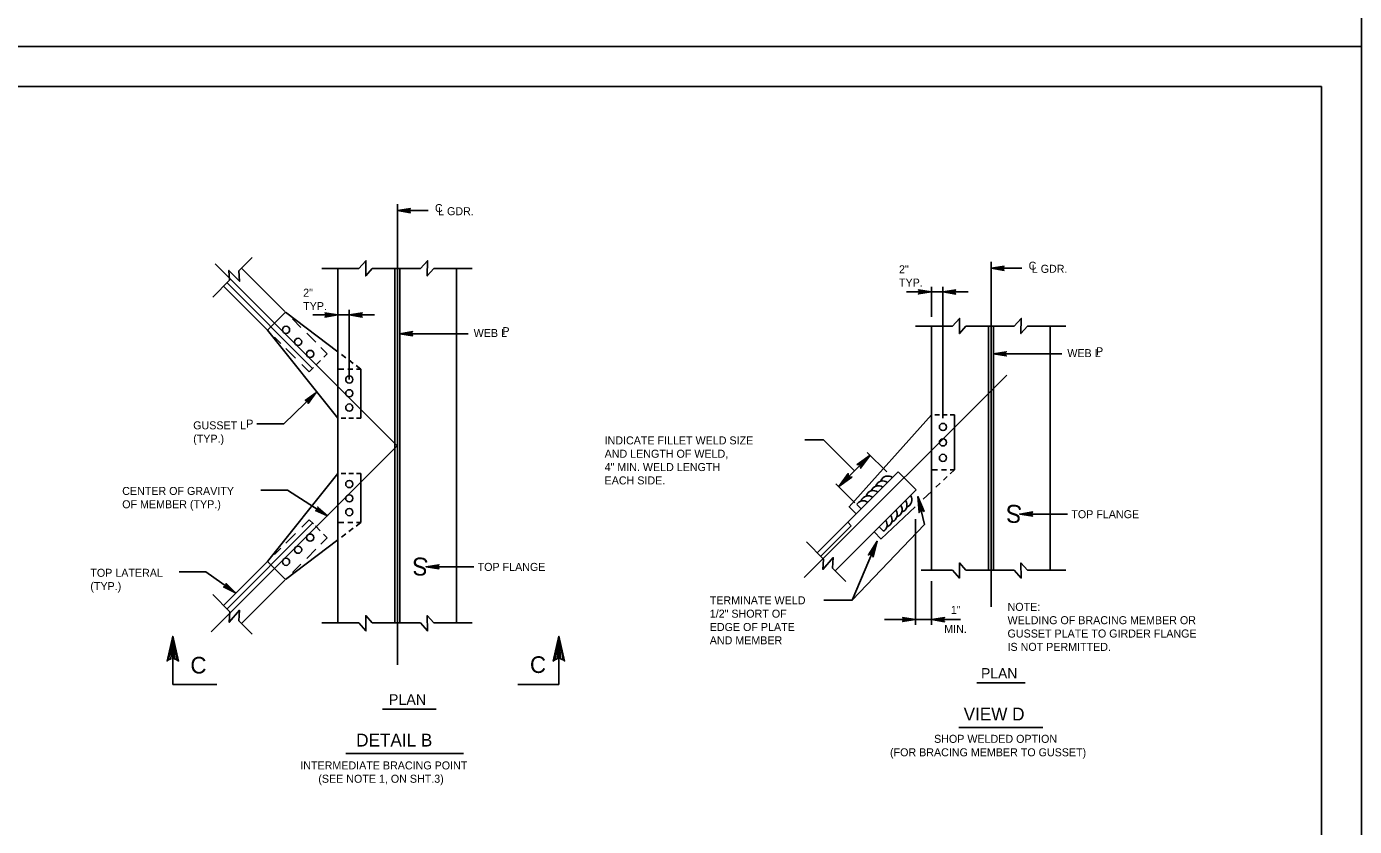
# Model space of a CAD drawing. Extents: x 30 to 2621, y -33 to 1155.
# Drawn here: x 1211.9 to 1709.8, y 268.6 to 568.5 of the extents above; entities that cross this region are included whole.
import ezdxf

# ---------------------------------------------------------------- set-up
doc = ezdxf.new("R2010")
doc.units = 0
doc.layers.add('1', color=7, linetype='Continuous')
doc.layers.add('PLT-BNDY', color=7, linetype='Continuous')

msp = doc.modelspace()

# ---------------------------------------------------------------- linework, layer by layer
at = {"layer": '1'}
for p, q in [((1697.5, 546), (911.5, 546)), ((1697.5, -18), (1697.5, 546)), ((1350.95, 492.79), (1350.95, 501.85)), ((1351.03, 499.48), (1362.48, 499.48)), ((1350.95, 329.19), (1350.95, 492.79)), ((1282.68, 479.55), (1350.92, 411.31)), ((1291.57, 476.94), (1296.56, 481.93)), ((1573.57, 471.19), (1573.57, 480.25)), ((1281.71, 467.08), (1288.05, 473.41)), ((1292.54, 477.91), (1308.82, 461.64)), ((1322.58, 477.74), (1336.53, 477.74)), ((1328.66, 344.89), (1328.66, 477.74)), ((1341.51, 477.74), (1359.63, 477.74)), ((1350, 477.74), (1350, 344.89)), ((1351.83, 477.74), (1351.83, 344.89)), ((1364.61, 477.74), (1378.98, 477.74)), ((1373.18, 344.89), (1373.18, 477.74)), ((1573.64, 477.87), (1585.09, 477.87)), ((1285.78, 471.15), (1302.22, 454.71)), ((1287.08, 472.45), (1319.19, 440.34)), ((1541.82, 469), (1555.46, 469)), ((1551.27, 459.7), (1551.27, 470.87)), ((1555.46, 421.65), (1555.46, 470.87)), ((1555.46, 469), (1564.96, 469)), ((1573.57, 350.96), (1573.57, 471.19)), ((1302.22, 454.71), (1308.98, 461.47)), ((1308.98, 461.47), (1328.66, 446.58)), ((1311.59, 458.86), (1314.8, 455.66)), ((1319.29, 460.36), (1332.93, 460.36)), ((1332.93, 436.17), (1332.93, 462.24)), ((1332.93, 460.36), (1342.44, 460.36)), ((1302.22, 454.71), (1328.66, 421.7)), ((1316.95, 453.5), (1320.35, 450.11)), ((1351.83, 453.33), (1377.46, 453.33)), ((1545.19, 456.14), (1559.14, 456.14)), ((1551.27, 364.65), (1551.27, 456.14)), ((1564.12, 456.14), (1582.24, 456.14)), ((1572.61, 456.14), (1572.61, 364.65)), ((1574.45, 456.14), (1574.45, 364.65)), ((1587.22, 456.14), (1601.59, 456.14)), ((1595.79, 364.65), (1595.79, 456.14)), ((1304.83, 452.1), (1307.27, 449.67)), ((1322.32, 448.14), (1324.65, 445.8)), ((1309.11, 447.83), (1312.8, 444.13)), ((1320.52, 441.67), (1322.18, 443.34)), ((1323.39, 444.54), (1324.65, 445.8)), ((1330.05, 445.53), (1331.61, 444.34)), ((1332.73, 443.5), (1334.41, 442.23)), ((1574.45, 445.79), (1600.07, 445.79)), ((1315.15, 441.79), (1317.89, 439.04)), ((1317.89, 439.04), (1319.45, 440.61)), ((1328.66, 440.11), (1330.94, 440.11)), ((1332.37, 440.11), (1334.28, 440.11)), ((1335.45, 441.44), (1337.2, 440.11)), ((1335.63, 440.11), (1337.2, 440.11)), ((1337.2, 440.11), (1337.2, 421.7)), ((1503.54, 361.89), (1579.43, 437.78)), ((1308.4, 419.61), (1320.44, 431.13)), ((1298.3, 419.61), (1308.4, 419.61)), ((1329.93, 421.7), (1331.58, 421.7)), ((1332.82, 421.7), (1334.47, 421.7)), ((1335.63, 421.7), (1337.2, 421.7)), ((1520.39, 388.4), (1551.27, 422.88)), ((1552.54, 422.88), (1554.19, 422.88)), ((1555.43, 422.88), (1557.08, 422.88)), ((1558.24, 422.88), (1559.82, 422.88)), ((1559.82, 402.28), (1559.82, 422.88)), ((1503.76, 413.54), (1510.73, 413.54)), ((1522.35, 401.92), (1510.73, 413.54)), ((1281.12, 341.52), (1350.92, 411.31)), ((1527.18, 408.84), (1534.45, 401.58)), ((1528.23, 407.79), (1516.48, 396.04)), ((1302.22, 367.91), (1328.66, 400.92)), ((1329.93, 400.92), (1331.58, 400.92)), ((1332.82, 400.92), (1334.47, 400.92)), ((1335.63, 400.92), (1337.2, 400.92)), ((1337.2, 382.51), (1337.2, 400.92)), ((1508.4, 371.24), (1538.72, 401.56)), ((1538.72, 401.56), (1545.48, 394.81)), ((1551.27, 402.28), (1553.55, 402.28)), ((1554.98, 402.28), (1556.89, 402.28)), ((1555.76, 398.46), (1557.18, 399.79)), ((1558.24, 402.28), (1559.82, 402.28)), ((1558.24, 400.8), (1559.82, 402.28)), ((1299.71, 394.69), (1309.81, 394.69)), ((1309.81, 394.69), (1324.79, 385.09)), ((1515.16, 364.48), (1545.48, 394.81)), ((1515.43, 397.09), (1522.52, 389.99)), ((1548.16, 391.31), (1551.24, 394.21)), ((1552.93, 395.79), (1554.54, 397.31)), ((1520.29, 388.5), (1522.97, 385.82)), ((1523.19, 389.33), (1524.84, 387.68)), ((1532.36, 376.43), (1545.18, 388.49)), ((1546.16, 392.3), (1548.6, 381.83)), ((1315.15, 380.84), (1317.89, 383.58)), ((1317.89, 383.58), (1319.48, 382)), ((1545.22, 344.17), (1545.22, 383.76)), ((1584.34, 385.73), (1602.18, 385.73)), ((1287.08, 350.18), (1319.19, 382.29)), ((1309.11, 374.8), (1312.8, 378.49)), ((1320.23, 381.25), (1322.04, 379.43)), ((1328.66, 382.51), (1330.94, 382.51)), ((1332.37, 382.51), (1334.28, 382.51)), ((1332.73, 379.13), (1334.41, 380.4)), ((1335.45, 381.19), (1337.2, 382.51)), ((1335.63, 382.51), (1337.2, 382.51)), ((1509.69, 369.94), (1521.11, 381.36)), ((1519.82, 382.66), (1521.11, 381.36)), ((1548.6, 381.83), (1521.46, 353.48)), ((1529.73, 379.06), (1532.42, 376.37)), ((1531.6, 380.92), (1533.25, 379.27)), ((1308.98, 361.15), (1328.66, 376.04)), ((1322.32, 374.49), (1324.65, 376.82)), ((1323.31, 378.16), (1324.65, 376.82)), ((1330.05, 377.1), (1331.61, 378.28)), ((1504.32, 375.31), (1510.79, 368.85)), ((1521.46, 353.48), (1530.81, 375.55)), ((1304.83, 370.52), (1307.27, 372.96)), ((1316.95, 369.12), (1320.35, 372.52)), ((1269.1, 364.09), (1279.2, 364.09)), ((1279.2, 364.09), (1290.21, 356.18)), ((1285.78, 351.47), (1302.22, 367.91)), ((1302.22, 367.91), (1308.98, 361.15)), ((1311.59, 363.76), (1314.8, 366.97)), ((1361.73, 365.97), (1379.57, 365.97)), ((1514.18, 365.46), (1519.18, 360.46)), ((1547.41, 364.65), (1559.14, 364.65)), ((1564.12, 364.65), (1582.24, 364.65)), ((1587.22, 364.65), (1601.59, 364.65)), ((1292.54, 344.71), (1308.82, 360.99)), ((1551.27, 344.17), (1551.27, 360.57)), ((1281.71, 355.55), (1288.17, 349.08)), ((1510.92, 353.48), (1521.46, 353.48)), ((1291.57, 345.69), (1296.56, 340.7)), ((1322.58, 344.89), (1336.53, 344.89)), ((1341.51, 344.89), (1359.63, 344.89)), ((1364.61, 344.89), (1378.98, 344.89)), ((1533.6, 346.15), (1545.22, 346.15)), ((1545.22, 346.15), (1551.27, 346.15)), ((1551.27, 346.15), (1562.16, 346.15)), ((1266.74, 321.84), (1266.74, 339.93)), ((1411.55, 321.84), (1411.55, 339.93)), ((1266.74, 321.84), (1283.22, 321.84)), ((1396.1, 321.84), (1411.55, 321.84)), ((1568.27, 322.41), (1586.36, 322.41)), ((1365.48, 312.63), (1345.35, 312.63)), ((1561.44, 305.67), (1592.96, 305.67)), ((1375.8, 295.89), (1331.65, 295.89))]:
    msp.add_line(p, q, dxfattribs=at)
for points in [[(1355.65, 498.9), (1355.47, 499.23), (1351.03, 499.48), (1355.65, 498.9), (1355.88, 498.7), (1351.03, 499.48), (1355.47, 499.7), (1355.63, 500.03), (1351.03, 499.48), (1355.88, 500.25), (1355.63, 500.03)], [(1341.51, 477.74), (1339.09, 475), (1339.16, 480.7), (1336.53, 477.74)], [(1364.61, 477.74), (1362.19, 475), (1362.26, 480.7), (1359.63, 477.74)], [(1578.26, 477.3), (1578.09, 477.63), (1573.64, 477.87), (1578.26, 477.3), (1578.49, 477.09), (1573.64, 477.87), (1578.08, 478.09), (1578.24, 478.42), (1573.64, 477.87), (1578.49, 478.65), (1578.24, 478.42)], [(1288.05, 473.41), (1287.82, 477.06), (1291.8, 472.98), (1291.57, 476.94)], [(1546.57, 469.58), (1546.74, 469.24), (1551.18, 469), (1546.57, 469.58), (1546.33, 469.78), (1551.18, 469), (1546.74, 468.78), (1546.58, 468.45), (1551.18, 469), (1546.33, 468.23), (1546.58, 468.45)], [(1560.07, 468.42), (1559.9, 468.75), (1555.46, 469), (1560.07, 468.42), (1560.31, 468.22), (1555.46, 469), (1559.89, 469.22), (1560.06, 469.55), (1555.46, 469), (1560.31, 469.77), (1560.06, 469.55)], [(1324.04, 460.94), (1324.21, 460.61), (1328.66, 460.36), (1324.04, 460.94), (1323.81, 461.14), (1328.66, 460.36), (1324.22, 460.14), (1324.06, 459.81), (1328.66, 460.36), (1323.81, 459.59), (1324.06, 459.81)], [(1337.54, 459.78), (1337.37, 460.12), (1332.93, 460.36), (1337.54, 459.78), (1337.78, 459.58), (1332.93, 460.36), (1337.37, 460.58), (1337.53, 460.91), (1332.93, 460.36), (1337.78, 461.13), (1337.53, 460.91)], [(1564.12, 456.14), (1561.7, 453.39), (1561.78, 459.1), (1559.14, 456.14)], [(1587.22, 456.14), (1584.8, 453.39), (1584.88, 459.1), (1582.24, 456.14)], [(1356.45, 452.76), (1356.27, 453.09), (1351.83, 453.33), (1356.45, 452.76), (1356.68, 452.55), (1351.83, 453.33), (1356.27, 453.55), (1356.43, 453.88), (1351.83, 453.33), (1356.68, 454.11), (1356.43, 453.88)], [(1579.06, 445.21), (1578.89, 445.54), (1574.45, 445.79), (1579.06, 445.21), (1579.3, 445), (1574.45, 445.79), (1578.88, 446.01), (1579.05, 446.34), (1574.45, 445.79), (1579.3, 446.56), (1579.05, 446.34)], [(1316.7, 428.36), (1317.06, 428.24), (1320.44, 431.13), (1316.7, 428.36), (1316.39, 428.34), (1320.44, 431.13), (1317.38, 427.9), (1317.5, 427.55), (1320.44, 431.13), (1317.47, 427.22), (1317.5, 427.55)], [(1523.71, 404.28), (1524.15, 404.14), (1528.23, 407.79), (1523.71, 404.28), (1523.33, 404.25), (1528.23, 407.79), (1524.56, 403.74), (1524.7, 403.31), (1528.23, 407.79), (1524.68, 402.9), (1524.7, 403.31)], [(1520.99, 399.55), (1520.55, 399.69), (1516.48, 396.04), (1520.99, 399.55), (1521.38, 399.58), (1516.48, 396.04), (1520.15, 400.09), (1520, 400.52), (1516.48, 396.04), (1520.03, 400.93), (1520, 400.52)], [(1546.75, 386.62), (1547.11, 386.91), (1546.16, 392.3), (1546.75, 386.62), (1546.58, 386.28), (1546.16, 392.3), (1547.66, 387.05), (1548.1, 386.95), (1546.16, 392.3), (1548.44, 386.71), (1548.1, 386.95)], [(1321.22, 388.06), (1321.18, 387.69), (1324.79, 385.09), (1321.22, 388.06), (1321.13, 388.36), (1324.79, 385.09), (1320.94, 387.3), (1320.62, 387.11), (1324.79, 385.09), (1320.29, 387.06), (1320.62, 387.11)], [(1588.95, 385.15), (1588.78, 385.49), (1584.34, 385.73), (1588.95, 385.15), (1589.19, 384.95), (1584.34, 385.73), (1588.78, 385.95), (1588.94, 386.28), (1584.34, 385.73), (1589.19, 386.5), (1588.94, 386.28)], [(1527.93, 370.6), (1528.4, 370.63), (1530.81, 375.55), (1527.93, 370.6), (1527.59, 370.43), (1530.81, 375.55), (1528.92, 370.41), (1529.22, 370.07), (1530.81, 375.55), (1529.35, 369.68), (1529.22, 370.07)], [(1510.79, 368.85), (1510.54, 364.95), (1514.41, 369.42), (1514.18, 365.46)], [(1366.34, 365.39), (1366.17, 365.72), (1361.73, 365.97), (1366.34, 365.39), (1366.57, 365.19), (1361.73, 365.97), (1366.16, 366.19), (1366.33, 366.52), (1361.73, 365.97), (1366.57, 366.74), (1366.33, 366.52)], [(1564.12, 364.65), (1561.7, 367.4), (1561.78, 361.69), (1559.14, 364.65)], [(1587.22, 364.65), (1584.8, 367.4), (1584.88, 361.69), (1582.24, 364.65)], [(1286.8, 359.34), (1286.75, 358.97), (1290.21, 356.18), (1286.8, 359.34), (1286.73, 359.64), (1290.21, 356.18), (1286.48, 358.59), (1286.16, 358.42), (1290.21, 356.18), (1285.82, 358.38), (1286.16, 358.42)], [(1288.17, 349.08), (1287.93, 345.19), (1291.8, 349.65), (1291.57, 345.69)], [(1341.51, 344.89), (1339.09, 347.63), (1339.16, 341.92), (1336.53, 344.89)], [(1364.61, 344.89), (1362.19, 347.63), (1362.26, 341.92), (1359.63, 344.89)], [(1540.6, 346.73), (1540.77, 346.39), (1545.22, 346.15), (1540.6, 346.73), (1540.37, 346.93), (1545.22, 346.15), (1540.78, 345.93), (1540.62, 345.6), (1545.22, 346.15), (1540.37, 345.38), (1540.62, 345.6)], [(1555.88, 345.57), (1555.71, 345.9), (1551.27, 346.15), (1555.88, 345.57), (1556.12, 345.37), (1551.27, 346.15), (1555.71, 346.37), (1555.87, 346.7), (1551.27, 346.15), (1556.12, 346.92), (1555.87, 346.7)], [(1265.14, 331.07), (1266.06, 331.4), (1266.74, 339.93), (1265.14, 331.07), (1264.58, 330.62), (1266.74, 339.93), (1267.34, 331.41), (1268.26, 331.09), (1266.74, 339.93), (1268.87, 330.62), (1268.26, 331.09)], [(1409.95, 331.07), (1410.87, 331.4), (1411.55, 339.93), (1409.95, 331.07), (1409.39, 330.62), (1411.55, 339.93), (1412.15, 331.41), (1413.07, 331.09), (1411.55, 339.93), (1413.68, 330.62), (1413.07, 331.09)]]:
    msp.add_lwpolyline(points, dxfattribs=at)
for centre in [(1309.22, 454.79), (1313.74, 450.27), (1318.26, 445.74), (1332.93, 436.17), (1332.93, 431.01), (1332.93, 425.65), (1555.54, 418.38), (1555.54, 412.6), (1555.54, 406.78), (1332.93, 396.98), (1332.93, 391.62), (1332.93, 386.46), (1313.74, 372.36), (1318.26, 376.88), (1309.22, 367.84)]:
    msp.add_circle(centre, 1.35, dxfattribs=at)
for centre, start, end in [((1534.92, 397.19), 54.1186, 158.9855), ((1529.44, 391.7), 54.1186, 158.9855), ((1531.28, 393.54), 54.1186, 158.9855), ((1533.03, 395.34), 54.1186, 158.9855), ((1525.6, 387.91), 54.1186, 148.4379), ((1527.49, 389.75), 54.1186, 158.9855), ((1537.46, 387.37), 291.0145, 35.8814), ((1539.26, 389.11), 291.0145, 35.8814), ((1541.1, 391.01), 291.0145, 35.8814), ((1533.67, 383.58), 291.0145, 35.8814), ((1535.61, 385.52), 291.0145, 35.8814), ((1531.82, 381.68), 301.5621, 35.8814)]:
    msp.add_arc(centre, 2.8, start, end, dxfattribs=at)
at = {"layer": 'PLT-BNDY'}
for points in [[(871.5, 1155), (1712.5, 1155), (1712.5, 561), (871.5, 561)], [(871.5, 561), (1712.5, 561), (1712.5, -33), (871.5, -33)]]:
    msp.add_lwpolyline(points, close=True, dxfattribs=at)

# ---------------------------------------------------------------- texts
at = {"layer": '1'}
for s, height, p in [('C', 3, (1365.06, 498.94)), ('L GDR.', 3, (1366.23, 497.77)), ('2"', 3, (1539.06, 476)), ('C', 3, (1587.67, 477.34)), ('L GDR.', 3, (1588.84, 476.17)), ('TYP.', 3, (1539.06, 471)), ('2"', 3, (1315.64, 467.2)), ('TYP.', 3, (1315.64, 462.2)), ('WEB L', 3, (1379.57, 452.1)), ('P', 3, (1390.34, 452.8)), ('P', 3, (1612.95, 445.25)), ('WEB L', 3, (1602.18, 444.55)), ('GUSSET L', 3, (1274.4, 417.48)), ('P', 3, (1294.3, 418.13)), ('(TYP.)', 3, (1274.4, 412.48)), ('INDICATE FILLET WELD SIZE', 3, (1428.67, 411.84)), ('AND LENGTH OF WELD,', 3, (1428.67, 406.84)), ('4" MIN. WELD LENGTH', 3, (1428.67, 401.84)), ('EACH SIDE.', 3, (1428.67, 396.84)), ('CENTER OF GRAVITY', 3, (1247.78, 392.89)), ('OF MEMBER (TYP.)', 3, (1247.78, 387.89)), ('TOP FLANGE', 3, (1603.68, 384.17)), ('TOP LATERAL', 3, (1235.84, 362.2)), ('TOP FLANGE', 3, (1381.06, 364.41)), ('(TYP.)', 3, (1235.84, 357.2)), ('TERMINATE WELD', 3, (1468.1, 351.88)), ('1/2" SHORT OF', 3, (1468.1, 346.88)), ('1"', 3, (1558.49, 348.28)), ('NOTE:', 3, (1579.76, 349.43)), ('EDGE OF PLATE', 3, (1468.1, 341.88)), ('MIN.', 3, (1556.02, 341.17)), ('WELDING OF BRACING MEMBER OR', 3, (1579.76, 344.43)), ('AND MEMBER', 3, (1468.1, 336.88)), ('GUSSET PLATE TO GIRDER FLANGE', 3, (1579.76, 339.43)), ('IS NOT PERMITTED.', 3, (1579.76, 334.43)), ('C', 6.24, (1273.35, 325.94)), ('C', 6.24, (1400.67, 326.15)), ('PLAN', 3.9, (1569.82, 324.07)), ('PLAN', 4, (1347.77, 314.19)), ('VIEW D', 4.8, (1563.3, 308.34)), ('DETAIL B', 4.8, (1335.51, 298.57)), ('SHOP WELDED OPTION', 3, (1552.21, 299.95)), ('(FOR BRACING MEMBER TO GUSSET)', 3, (1535.69, 294.9)), ('INTERMEDIATE BRACING POINT', 3, (1314.56, 289.98)), ('(SEE NOTE 1, ON SHT.3)', 3, (1321.32, 284.98))]:
    msp.add_text(s, height=height, dxfattribs=at).set_placement(p)
for p in [(1585.39, 388.96), (1362.78, 369.19)]:
    msp.add_text('S', height=6.72, rotation=176.2424, dxfattribs=at).set_placement(p)

doc.saveas('drawing.dxf')
